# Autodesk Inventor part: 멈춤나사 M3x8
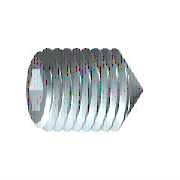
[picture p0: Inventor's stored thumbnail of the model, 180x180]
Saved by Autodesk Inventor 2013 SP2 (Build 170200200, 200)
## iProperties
Created: 2012-02
Part Number: 멈춤나사 M3x8
Material: 강철, 연강
Description: 6각 소켓 머리 없는 멈춤 나사
Document SubType Name: Modeling
Standard: KS B 1028
Designer: mduedu
Standards Organization: KS
Language: ko-KR
Size Designation: 원추점 M3x8
Categories: <MemberInstance><Categories><Category DisplayName="조임쇠" InternalName="e4da775c-781d-43d5-af7c-5136215cf5a6" Mnemonic="FSTN"><Category DisplayName="볼트" InternalN
Density: 7.86 g/cm^3
Mass: 0.360339 g
Surface Area: 0.888172 cm^2
Volume: 0.0458447 cm^3
IsCustomPart: 1
Author: mduedu
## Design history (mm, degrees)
sketch "스케치1"
  geometry: L1 (0, 0)-(5.5, 0); L2 (8, 0.866)-(8, 1.5); L3 (8, 1.5)-(0, 1.5); L4 (8, 0.866)-(6, 0.866); L5 (6, 0.866)-(5.5, 0); L6 (0, -0.3)-(0, 1.8) reference; L7 (0, 1.5)-(0, 0)
  constraints: 13 end point, 3 parallel, 1 collinear, 1 perpendicular, 1 point on line
  dimensions: "d0" = 2 distance of L2.start L4.end (= INTI); "d1" = 60 deg angle of L5 L1; "d2" = 3 diameter of L3 L1 (= NND); "d3" = 1.73205 diameter of L4 L1 (= 1.1547 x SW); "d5" = 8 distance from line of L2 L3.end (= NLG)
revolve "본체" sketch "스케치1" stored, may be unused: angle "d6" = 90 deg
sketch "스케치2"
  geometry: L1 (-0.433, 0.75)-(0.433, 0.75); L2 (0.433, 0.75)-(0.866, 0); L3 (0.866, 0)-(0.433, -0.75); L4 (0.433, -0.75)-(-0.433, -0.75); L5 (-0.433, -0.75)-(-0.866, 0); L6 (-0.866, 0)-(-0.433, 0.75); 3 further points
  constraints: 12 end point, 1 coincident, 1 horizontal, 13 other
extrude "슬롯" join sketch "스케치2" taper "d7" = 0 deg; stored distance "d21" = 10
workaxis "Work Axis1"
workplane "Work Plane1"
sketch "스케치5"
  geometry: L1 (-4, -0.15)-(-2.65, -1.5) reference; L2 (-4, 0.15)-(-2.65, 1.5) reference; L3 (-2.65, 1.5)-(-4.15, 0); L4 (-2.65, -1.5)-(-4.15, 0); 1 further point
  constraints: 4 end point, 1 horizontal alignment, 1 perpendicular
node "작업점1"
body "Solid1"
feature "스레드" dims "d12" = 8 (= NLG), "d13" = 0
chamfer "모따기1" distance "d8" = 1.35 (computed from NND, SPD, FAWI); stored, may be unused: angle "d9" = 45 deg (= FAWI), second distance "d34" = 1.35 (computed from NND, SPD, FAWI)
chamfer "모따기2" distance "d10" = 0.30673 (= -0.5 x GD1 + 0.5 x NND); stored, may be unused: angle "d11" = 45 deg (= FAWI), second distance "d35" = 0.30673 (= -0.5 x GD1 + 0.5 x NND)
other parameters: "NND" = 3 [user parameter; used in 5 equation terms], "NLG" = 8 [user parameter; used in 2 equation terms], "INTI" = 2 [user parameter; used in 1 equation term], "FAWI" = 45 deg [user parameter; used in 4 equation terms], "SW" = 1.5 [user parameter; used in 2 equation terms], "GD1" = 2.38655 (= THREADDIA - 1.2269 x PTC) [user parameter; used in 2 equation terms], "d4" = 0, "FAWI1" = 45 deg [user parameter], "SPD" = 0.3 [user parameter; used in 2 equation terms], "d36" = 0, "d37" = 0, "GUL" = 0.30673 (= 0.61345 x PTC) [user parameter], "TOA" = 30 deg [user parameter], "THREADDIA" = 3 [user parameter; used in 1 equation term], "PTC" = 0.5 [user parameter; used in 4 equation terms], "GAL" = 0.30673 (= 0.61345 x PTC) [user parameter], "E0" = 1.7325 (= 1.155 x SW) [user parameter]
